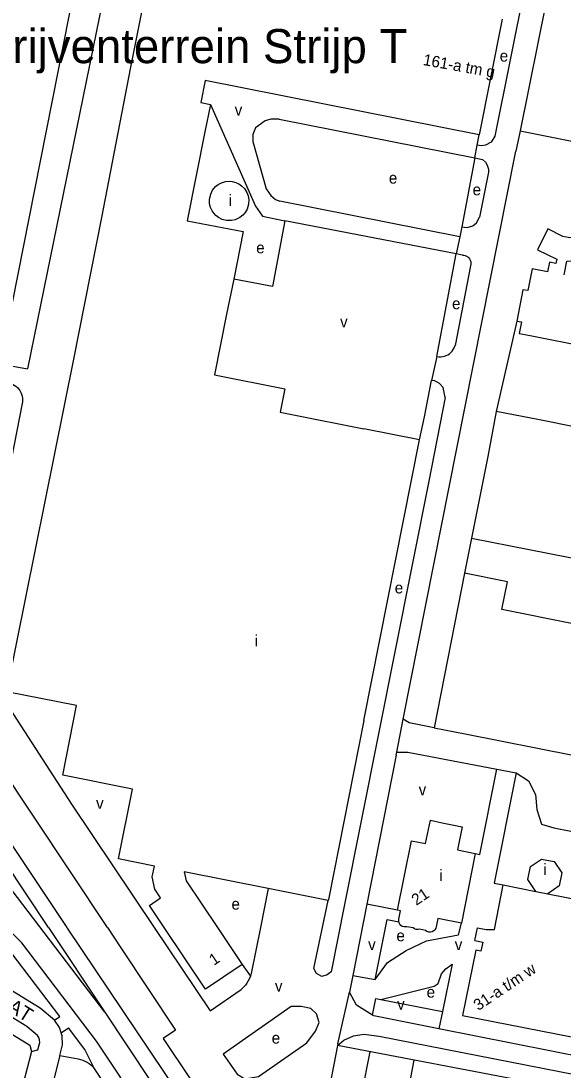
# Model space of a CAD drawing. Extents: x 158356 to 159894, y 383831 to 385260.
# Drawn here: x 159379.2 to 159570.1, y 384449.8 to 384819.2 of the extents above; entities that cross this region are included whole.
import ezdxf

# ---------------------------------------------------------------- set-up
doc = ezdxf.new("R2010")
doc.units = 0
for name, color, linetype in [('BLT_Basislijn', 7, 'Continuous'), ('BLT_Bebouwing', 7, 'Continuous'), ('BLT_Centroide', 7, 'Continuous'), ('BLT_Huisnummer', 7, 'Continuous'), ('BLT_Huisnummer_reeks', 7, 'Continuous'), ('BLT_Onderverdeling_panden', 7, 'Continuous'), ('BLT_Sport_parknaam', 7, 'Continuous'), ('BLT_Straatnaam', 7, 'Continuous')]:
    doc.layers.add(name, color=color, linetype=linetype)

msp = doc.modelspace()

# ---------------------------------------------------------------- linework, layer by layer
at = {"layer": 'BLT_Basislijn'}
for p, q in [((159470.16, 384784.63), (159539.08, 384770.95)), ((159539.91, 384775.41), (159540.57, 384779.03)), ((159554.98, 384780.49), (159553.54, 384773.38)), ((159554.98, 384780.49), (159656.42, 384760.21)), ((159539.08, 384770.95), (159539.91, 384775.41)), ((159532.64, 384668.08), (159553.54, 384773.38)), ((159539.08, 384770.95), (159534.48, 384746.64)), ((159539.08, 384770.95), (159541.78, 384770.41)), ((159543.82, 384765.88), (159540.72, 384750.03)), ((159533.82, 384743.16), (159470.37, 384755.67)), ((159532.53, 384737.18), (159472.14, 384748.74)), ((159534.48, 384746.64), (159533.82, 384743.16)), ((159533.82, 384743.16), (159532.53, 384737.18)), ((159525.72, 384701.01), (159532.53, 384737.18)), ((159534.73, 384736.76), (159532.53, 384737.18)), ((159537.57, 384732.92), (159532.09, 384704.9)), ((159553.82, 384713.52), (159546.6, 384681.7)), ((159525.72, 384701.01), (159523.79, 384692.61)), ((159371.93, 384698.43), (159381.53, 384696.68)), ((159379.61, 384684.48), (159372.02, 384645.44)), ((159513.83, 384573.34), (159532.64, 384668.08)), ((159537.93, 384637.08), (159535.46, 384624.68)), ((159409.74, 384500), (159332.15, 384615.97)), ((159511.54, 384561.69), (159513.83, 384573.34)), ((159511.34, 384560.7), (159501.01, 384508.19)), ((159511.34, 384560.7), (159511.54, 384561.69)), ((159546.79, 384555.69), (159553.62, 384554.38)), ((159466.28, 384513.64), (159463.54, 384500)), ((159501.01, 384508.19), (159496.07, 384483.06)), ((159511.87, 384506.01), (159501.01, 384508.19)), ((159503.97, 384481.62), (159508.23, 384502.75)), ((159508.23, 384502.75), (159512.31, 384501.92)), ((159533.33, 384497.37), (159534.31, 384501.51)), ((159395.34, 384500), (159395.52, 384499.75)), ((159395.52, 384499.75), (159454.74, 384411.48)), ((159463.54, 384500), (159460.27, 384483.77)), ((159514.9, 384491.86), (159521.99, 384495.28)), ((159521.99, 384495.28), (159533.33, 384497.37)), ((159508.27, 384487.6), (159514.9, 384491.86)), ((159457.15, 384486.89), (159460.01, 384482.88)), ((159503.97, 384481.62), (159508.27, 384487.6)), ((159460.27, 384483.77), (159460.01, 384482.88)), ((159496.07, 384483.06), (159494.91, 384477.15)), ((159496.07, 384483.06), (159503.97, 384481.62)), ((159490.84, 384458.97), (159494.91, 384477.15)), ((159505.99, 384474.66), (159527.65, 384470.42)), ((159391.07, 384467.32), (159392.92, 384468.61)), ((159527.65, 384470.42), (159526.37, 384464.28)), ((159393.37, 384462.84), (159395.94, 384464.62)), ((159596.78, 384450.34), (159526.37, 384464.28)), ((159490.74, 384458.44), (159486.07, 384434.39)), ((159490.84, 384458.97), (159490.74, 384458.44)), ((159559.56, 384445.29), (159490.74, 384458.44)), ((159382.91, 384456.26), (159376.56, 384431.88)), ((159392.88, 384454.89), (159387.97, 384435.21)), ((159392.88, 384454.89), (159399.35, 384453.71)), ((159502.05, 384456.17), (159498.56, 384438.73)), ((159405.38, 384449.78), (159417.63, 384431.34)), ((159508.8, 384405.78), (159517.7, 384453.25))]:
    msp.add_line(p, q, dxfattribs=at)
for points in [[(159438.93, 384967.17), (159437.75, 384960.87), (159435.49, 384961.29), (159381.53, 384696.68)], [(159579.93, 384843.97), (159571.7, 384841.59), (159566.54, 384835.45), (159564.31, 384826.63), (159554.98, 384780.49)], [(159551.75, 384837.34), (159552.37, 384837.98), (159553.02, 384837.75), (159556.78, 384831.86), (159546.06, 384778.64), (159544.8, 384776.49), (159542.76, 384775.45), (159541.27, 384775.17), (159539.91, 384775.41)], [(159445.92, 384789.81), (159461.81, 384753.92), (159464.22, 384750.4), (159472.14, 384748.74)], [(159470.16, 384784.63), (159467.25, 384784.63), (159465.2, 384783.96), (159461.78, 384781.5), (159460.91, 384779.21), (159460.88, 384776.69), (159465.54, 384760.05), (159467.19, 384757.66), (159468.84, 384756.32), (159470.37, 384755.67)], [(159541.78, 384770.41), (159542.83, 384769.44), (159543.38, 384768.41), (159543.84, 384767.01), (159543.82, 384765.88)], [(159534.48, 384746.64), (159536.32, 384746.42), (159538.34, 384747.04), (159539.66, 384748.14), (159540.72, 384750.03)], [(159472.14, 384748.74), (159467.81, 384725.72), (159454.12, 384728.3)], [(159534.73, 384736.76), (159535.22, 384736.71), (159535.7, 384736.57), (159536.14, 384736.37), (159536.55, 384736.09), (159536.91, 384735.75), (159537.2, 384735.36), (159537.43, 384734.93), (159537.59, 384734.46), (159537.67, 384733.97), (159537.67, 384733.48), (159537.57, 384732.92)], [(159525.72, 384701.01), (159526.37, 384700.92), (159527.04, 384700.91), (159527.7, 384700.98), (159528.34, 384701.12), (159528.96, 384701.35), (159529.56, 384701.64), (159530.11, 384702.01), (159530.61, 384702.44), (159531.06, 384702.93), (159531.45, 384703.46), (159531.77, 384704.04), (159532.02, 384704.66), (159532.09, 384704.9)], [(159374.94, 384691.71), (159375.61, 384691.53), (159376.26, 384691.28), (159376.87, 384690.95), (159377.44, 384690.55), (159377.96, 384690.1), (159378.43, 384689.58), (159378.83, 384689.01), (159379.17, 384688.4), (159379.43, 384687.76), (159379.62, 384687.09), (159379.73, 384686.41), (159379.76, 384685.71), (159379.71, 384685.02), (159379.61, 384684.48)], [(159519.58, 384671.66), (159521.34, 384679.74), (159523.79, 384692.61)], [(159528.56, 384686.64), (159527.95, 384690.12), (159526.63, 384691.5), (159524.91, 384692.45), (159523.79, 384692.61)], [(159528.56, 384686.64), (159522.8, 384657.18), (159493.12, 384508.02), (159488.43, 384484.39), (159487.1, 384483.25), (159485.19, 384482.74), (159483.26, 384483.81), (159482.38, 384485.54), (159487.42, 384509.45)], [(159373.95, 384578.96), (159397.06, 384543.35), (159426.1, 384500)], [(159524.69, 384570.32), (159515.87, 384572.07), (159513.83, 384573.34)], [(159355.82, 384562.28), (159359.21, 384559.77), (159362.31, 384556.68), (159365.63, 384551.72), (159367.76, 384546.94), (159375.12, 384530.26), (159395.34, 384500)], [(159511.54, 384561.69), (159515.48, 384561.69), (159546.79, 384555.69)], [(159539.2, 384526.01), (159540.8, 384525.69), (159546.79, 384555.69)], [(159553.62, 384554.38), (159545.84, 384515.53), (159549.04, 384514.96)], [(159553.62, 384554.38), (159557.99, 384551.6), (159560.42, 384546.76), (159560.9, 384541.51), (159562.53, 384536.39), (159566.87, 384535.08), (159602.74, 384528.02), (159606.87, 384526.05), (159608.63, 384523.94), (159609.83, 384520.08), (159609.82, 384517.39), (159607.25, 384503.27)], [(159388.95, 384500), (159365.65, 384534.86), (159364.86, 384532.44), (159363.35, 384529.22), (159362.78, 384528.28)], [(159408.73, 384470.2), (159370, 384520.91), (159362.78, 384528.28)], [(159391.07, 384467.32), (159386, 384471.58), (159313.34, 384516.16)], [(159392.92, 384468.61), (159375.79, 384491.21), (159351.59, 384515.23)], [(159476.29, 384336.47), (159467.84, 384354.16), (159459.96, 384370.94), (159444.22, 384401.18), (159439.12, 384409.82), (159405.78, 384459.91), (159379.56, 384494.51), (159361.43, 384512.52)], [(159388.95, 384500), (159408.73, 384470.2)], [(159409.74, 384500), (159414.36, 384492.83), (159433.65, 384463.85), (159429.26, 384460.91), (159458.09, 384417.86), (159461.96, 384420.65), (159465.15, 384416.79)], [(159426.1, 384500), (159445.83, 384470.56), (159456.78, 384478.18)], [(159505.99, 384474.66), (159524.77, 384479.32), (159526.17, 384480.26), (159527.27, 384483.69), (159528.86, 384485.36), (159531.11, 384487.03), (159527.65, 384470.42)], [(159382.91, 384456.26), (159385.13, 384456.88), (159385.8, 384459.47), (159385.76, 384460.38), (159385.47, 384461.28), (159385.02, 384461.95), (159381.31, 384465.07), (159349.1, 384484.83)], [(159344.6, 384481.65), (159382.38, 384458.56), (159382.91, 384456.26)], [(159460.01, 384482.88), (159459.67, 384482.02), (159459.26, 384481.19), (159458.77, 384480.4), (159458.23, 384479.66), (159457.62, 384478.96), (159456.95, 384478.32), (159456.78, 384478.18)], [(159502.97, 384469.12), (159497.36, 384472.6), (159494.91, 384477.15)], [(159502.97, 384469.12), (159504.22, 384474.99), (159505.99, 384474.66)], [(159408.73, 384470.2), (159448.57, 384410.17), (159454.89, 384398.29), (159457.18, 384394.95)], [(159526.37, 384464.28), (159503.48, 384468.8), (159502.97, 384469.12)], [(159393.37, 384462.84), (159392.74, 384464.8), (159391.07, 384467.32)], [(159405.38, 384449.78), (159401.71, 384457.02), (159395.94, 384464.62)], [(159392.88, 384454.89), (159393.84, 384458.62), (159393.71, 384461.81), (159393.37, 384462.84)], [(159490.74, 384458.44), (159492.96, 384460.31), (159496.32, 384461.8), (159500.01, 384462.43), (159505.32, 384461.69), (159586.21, 384445.87)], [(159399.35, 384453.71), (159400.18, 384453.53), (159400.98, 384453.28), (159401.76, 384452.95), (159402.5, 384452.55), (159403.21, 384452.08), (159403.86, 384451.55), (159404.46, 384450.96), (159405, 384450.31), (159405.38, 384449.78)]]:
    msp.add_lwpolyline(points, dxfattribs=at)
msp.add_lwpolyline([(159474.4, 384472.1), (159450.37, 384455.33), (159455.3, 384448.27), (159458, 384446.65), (159462.86, 384447.46), (159479.92, 384459.35), (159482.93, 384463.41), (159484.23, 384466.53), (159483.33, 384469.59), (159481.27, 384471.44), (159477.91, 384472.2)], close=True, dxfattribs=at)
at = {"layer": 'BLT_Bebouwing'}
for p, q in [((159548.66, 384819.86), (159540.57, 384779.03)), ((159540.57, 384779.03), (159444.05, 384798.18)), ((159445.92, 384789.81), (159444.01, 384780.15)), ((159457.48, 384745.06), (159454.12, 384728.3)), ((159564.66, 384730.83), (159559.21, 384731.88)), ((159454.12, 384728.3), (159451.63, 384715.89)), ((159374.24, 384582.91), (159397.82, 384700.1)), ((159546.6, 384681.7), (159543.66, 384665.79)), ((159519.58, 384671.66), (159500, 384675.57)), ((159500, 384572.9), (159519.58, 384671.66)), ((159537.93, 384637.08), (159606.93, 384623.36)), ((159535.46, 384624.68), (159524.69, 384570.32)), ((159524.69, 384570.32), (159535.63, 384568.14)), ((159535.63, 384568.14), (159573.58, 384560.59)), ((159418.49, 384548.67), (159393.96, 384553.55)), ((159521.73, 384529.52), (159523.4, 384537.7)), ((159523.4, 384537.7), (159527.56, 384536.87)), ((159527.56, 384536.87), (159534.64, 384535.46)), ((159534.64, 384535.46), (159533, 384527.25)), ((159511.87, 384506.01), (159516.79, 384530.5)), ((159516.79, 384530.5), (159521.73, 384529.52)), ((159533, 384527.25), (159539.2, 384526.01)), ((159539.2, 384526.01), (159534.31, 384501.51)), ((159466.28, 384513.64), (159436.67, 384519.51)), ((159487.42, 384509.45), (159466.28, 384513.64)), ((159545.96, 384499.26), (159549.04, 384514.96)), ((159549.04, 384514.96), (159560.52, 384512.65)), ((159564.79, 384511.8), (159587.2, 384507.3)), ((159512.91, 384505.81), (159511.87, 384506.01)), ((159534.31, 384501.51), (159526.01, 384503.18)), ((159448.38, 384500), (159457.15, 384486.89)), ((159539.1, 384495.4), (159539.97, 384499.85)), ((159534.72, 384468.97), (159598.04, 384456.49))]:
    msp.add_line(p, q, dxfattribs=at)
for points in [[(159376.06, 384719.31), (159414.39, 384912.96), (159428.71, 384985.2)], [(159417.89, 384802.95), (159426.12, 384844.25)], [(159397.82, 384700.1), (159407.71, 384750), (159417.89, 384802.95)], [(159444.05, 384798.18), (159442.52, 384790.47), (159445.92, 384789.81)], [(159444.01, 384780.15), (159437.79, 384748.77), (159457.48, 384745.06)], [(159570.52, 384729.73), (159571.5, 384734.64), (159577.46, 384734.93), (159576.95, 384743.17), (159572.52, 384742.86), (159570.05, 384743.25), (159564.76, 384745.99), (159561.12, 384738.54), (159567.9, 384735.33), (159567.59, 384733.79), (159565.33, 384734.24), (159564.66, 384730.83)], [(159559.21, 384731.88), (159557.69, 384724.21), (159556, 384724.55), (159553.82, 384713.52)], [(159451.63, 384715.89), (159447.36, 384694.56), (159472.13, 384689.63)], [(159553.82, 384713.52), (159555.5, 384713.18), (159554.71, 384709.18), (159558.58, 384708.41), (159596.9, 384700.82)], [(159472.13, 384689.63), (159470.5, 384681.46), (159475.22, 384680.52), (159500, 384675.57)], [(159615.89, 384667.84), (159561.77, 384678.67), (159546.6, 384681.7)], [(159543.66, 384665.79), (159537.93, 384637.08)], [(159601.3, 384595), (159596.45, 384595.96), (159597.67, 384602.12), (159548.61, 384611.88), (159550.55, 384621.67), (159535.46, 384624.68)], [(159393.96, 384553.55), (159398.81, 384578.09), (159374.24, 384582.91)], [(159500, 384572.9), (159487.6, 384510.37), (159487.49, 384509.79), (159487.42, 384509.45)], [(159426.18, 384521.59), (159413.6, 384524.11), (159418.49, 384548.67)], [(159560.52, 384512.65), (159557.7, 384516.83), (159558.61, 384521.44), (159562.49, 384524.01), (159567.04, 384523.15)], [(159429.61, 384500), (159424.44, 384507.73), (159428.37, 384510.37), (159426.3, 384513.46), (159425.44, 384517.8), (159426.18, 384521.59)], [(159567.04, 384523.15), (159569.7, 384519.23), (159568.79, 384514.6), (159564.79, 384511.8)], [(159436.67, 384519.51), (159437.39, 384516.42), (159448.38, 384500)], [(159512.31, 384501.92), (159512.25, 384502.23), (159512.32, 384502.86), (159512.91, 384505.81)], [(159526.01, 384503.18), (159525.42, 384500.23), (159525.27, 384499.68), (159524.98, 384499.18), (159524.58, 384498.78), (159524.04, 384498.47), (159523.48, 384498.33), (159522.82, 384498.36), (159522.19, 384498.59), (159521.71, 384498.94), (159519.52, 384499.38), (159519.04, 384499.24), (159518.42, 384499.25), (159517.79, 384499.48), (159517.36, 384499.81), (159515.16, 384500.25), (159514.65, 384500.14), (159514.04, 384500.16), (159513.46, 384500.36), (159512.97, 384500.69), (159512.6, 384501.13), (159512.35, 384501.66), (159512.31, 384501.92)], [(159457.15, 384486.89), (159444.18, 384478.21), (159429.61, 384500)], [(159539.97, 384499.85), (159543.04, 384499.23), (159545.96, 384499.26)], [(159539.1, 384495.4), (159541.83, 384494.85), (159541.18, 384491.64), (159539.36, 384492.01), (159534.72, 384468.97)]]:
    msp.add_lwpolyline(points, dxfattribs=at)
msp.add_lwpolyline([(159452.53, 384762.73), (159453.63, 384762.65), (159454.84, 384762.35), (159455.89, 384761.85), (159456.88, 384761.17), (159457.89, 384760.18), (159458.75, 384758.83), (159459.21, 384757.65), (159459.46, 384756.27), (159459.4, 384754.62), (159458.91, 384752.94), (159458.14, 384751.79), (159457.34, 384750.8), (159456.29, 384750), (159455.61, 384749.62), (159454.68, 384749.2), (159453.3, 384748.9), (159451.65, 384748.87), (159450.01, 384749.29), (159448.78, 384750), (159447.83, 384750.66), (159447.23, 384751.4), (159446.52, 384752.37), (159445.99, 384753.55), (159445.66, 384754.81), (159445.66, 384756.46), (159446.02, 384758.17), (159446.68, 384759.54), (159447.72, 384760.84), (159448.71, 384761.58), (159449.84, 384762.18), (159451.24, 384762.6)], close=True, dxfattribs=at)
at = {"layer": 'BLT_Onderverdeling_panden'}
msp.add_line((159560.52, 384512.65), (159564.79, 384511.8), dxfattribs=at)

# ---------------------------------------------------------------- texts
at = {"layer": 'BLT_Centroide'}
for s, p in [('e', (159547.82, 384804.89)), ('v', (159454.47, 384785.88)), ('e', (159508.77, 384761.92)), ('e', (159538.28, 384757.8)), ('i', (159452.34, 384754.04)), ('e', (159462.05, 384737.36)), ('e', (159531.03, 384717.69)), ('v', (159491.59, 384711.27)), ('e', (159510.85, 384617.6)), ('i', (159461.45, 384598.94)), ('v', (159405.66, 384541.75)), ('i', (159526.52, 384516.31)), ('i', (159563.16, 384518.43)), ('e', (159453.35, 384506.26)), ('e', (159511.43, 384495.11)), ('e', (159522.07, 384475.25)), ('e', (159467.51, 384459.08))]:
    msp.add_text(s, height=4, dxfattribs=at).set_placement(p)
for p in [(159519.3, 384546.53), (159501.51, 384491.97), (159532.02, 384491.97), (159468.69, 384477.36), (159511.72, 384470.99)]:
    msp.add_text('v', height=4, rotation=1, dxfattribs=at).set_placement(p)
at = {"layer": 'BLT_Huisnummer'}
for s, p in [('21', (159518.43, 384507.55)), ('1', (159447.15, 384486.43))]:
    msp.add_text(s, height=4, rotation=33.7919, dxfattribs=at).set_placement(p)
at = {"layer": 'BLT_Huisnummer_reeks'}
for s, rotation, p in [('161-a tm g', 349.7842, (159520.61, 384803.7)), ('31-a t/m w', 33.7919, (159540.28, 384470.51))]:
    msp.add_text(s, height=4, rotation=rotation, dxfattribs=at).set_placement(p)
at = {"layer": 'BLT_Sport_parknaam'}
msp.add_text('Bedrijventerrein Strijp T', height=12, dxfattribs=at).set_placement((159347.62, 384804.32))
at = {"layer": 'BLT_Straatnaam'}
msp.add_text('HALVEMAANSTRAAT', height=5, rotation=327.9266, dxfattribs=at).set_placement((159324.06, 384502.31))

doc.saveas('drawing.dxf')
